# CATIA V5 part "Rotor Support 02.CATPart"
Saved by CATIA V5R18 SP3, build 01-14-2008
Part number: Table Center Support
Bounding box of the stored display mesh (mm): x -49 to 49, y 0 to 50, z -49 to 49
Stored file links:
  E:\#00 CATIA V5 Movie\#03 CATIA V5 Data\#07 KIN\Balance Unit (1)\Rotor Support 02.CATPart
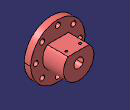
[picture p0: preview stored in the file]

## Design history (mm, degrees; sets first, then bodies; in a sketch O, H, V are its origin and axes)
Body1 (main body)
  Sketch1 on zx-plane, origin (0, 0, 0), H (-1, 0, 0), V (0, 0, 1)
    circle A1 centre (0, 0) radius 49
    radius A1 = 49
  Pad1: profile Sketch1, direction (0, 1, 0), length 12
  Sketch2 on start face of Pad1, origin (0, 0, 0), H (1, 0, 0), V (0, 0, 1)
    circle A1 centre (0, 0) radius 21.5
    radius A1 = 21.5
  Pocket1: profile Sketch2, direction (0, 1, 0), length 7
  Sketch3 on end face of Pad1, origin (0, 12, 0), H (-1, 0, 0), V (0, 0, 1)
    arc A1 centre (0, 0) radius 27.5 from (-19.3907, 19.5) to (19.3907, 19.5) ccw
    line L1 (-19.3907, 19.5) -> (19.3907, 19.5)
    radius A1 = 27.5
    distance L1 H = 19.5
    horizontal: L1 H
  Pad2: profile Sketch3, direction (0, 1, 0), length 38
  Sketch4 on end face of Pocket1, origin (0, 7, 0), H (1, 0, 0), V (0, 0, 1)
    circle A1 centre (0, 0) radius 15
    radius A1 = 15
  Pocket2: profile Sketch4, direction (0, 1, 0), length 18
  Sketch5 on end face of Pad2, origin (-9.5492, 50, -3.4273), H (1, 0, 0), V (0, 0, -1)
    point P1 (9.5492, -3.4273)
    reference projected circle E1 centre (9.5492, -3.4273) radius 49 from edge [face of Pad1 from Sketch1.A1 | end face of Pad1]
    concentricity: E1 P1
  Hole1: placed by Sketch5, at (0, 50, 0) direction (0, -1, 0), diameter 17.294, through (limit type 6), threaded "M20", thread diameter 20, thread depth 10, pitch 2.5
  Sketch6 on end face of Pad1, origin (0, 12, 0), H (-1, 0, 0), V (0, 0, 1)
    construction circle A1 centre (0, 0) radius 40
    circle A2 centre (0, 40) radius 4.5
    point P1 (0, 40)
    circle A3 centre (40, 0) radius 4.5
    point P2 (40, 0)
    circle A4 centre (-40, 0) radius 4.5
    point P3 (-40, 0)
    circle A5 centre (0, -40) radius 4.5
    point P4 (0, -40)
    construction line L1 (0, 0) -> (31.4663, -31.4663)
    point P5 (31.4663, -31.4663)
    circle A6 centre (28.2843, -28.2843) radius 4.5
    point P6 (28.2843, -28.2843)
    circle A7 centre (28.2843, 28.2843) radius 4.5
    circle A8 centre (-28.2843, 28.2843) radius 4.5
    circle A9 centre (-28.2843, -28.2843) radius 4.5
    radius A2 = 4.5
    radius A3 = 4.5
    radius A5 = 4.5
    radius A4 = 4.5
    radius A6 = 4.5
    radius A1 = 40
    angle L1 H = 45
    coincidence: P1 A1, P1 V, P2 A1, P2 H, P3 A1, P3 H, P4 A1, P4 V, A6 P5, P6 L1, P6 A1
    symmetry: A6 A7 H, A7 A8 V, A6 A9 V
  Pocket3: profile Sketch6, direction (0, -1, 0), through (limit type 6)
  Sketch7 on face of Pad2 from Sketch3.L1, origin (-12.5, 40, 19.5), H (1, 0, 0), V (0, 1, 0)
    point P1 (0, 0)
    reference projected point E1 (0, 0) from Sketch8.P1
    coincidence: E1 P1
  Hole2: placed by Sketch7, at (-12.5, 40, 19.5) direction (0, 0, -1), diameter 4.134, depth 12, V-bottom angle 120, threaded "M5", thread diameter 5, thread depth 12, pitch 0.8
  Sketch8 on face of Pad2 from Sketch3.L1, origin (0, 0, 19.5), H (1, 0, 0), V (0, 1, 0)
    construction line L1 (-12.5, 40) -> (12.5, 40)
    point P1 (-12.5, 40)
    point P2 (12.5, 40)
    reference projected line E1 (-19.3907, 50) -> (19.3907, 50) from edge [face of Pad2 from Sketch3.L1 | end face of Pad2]
    length L1 = 25
    distance L1 E1 = 10
    horizontal: L1 H
    symmetry: P2 P1 V
  UserPattern1: of Hole2, copies 2, at the points of Sketch8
